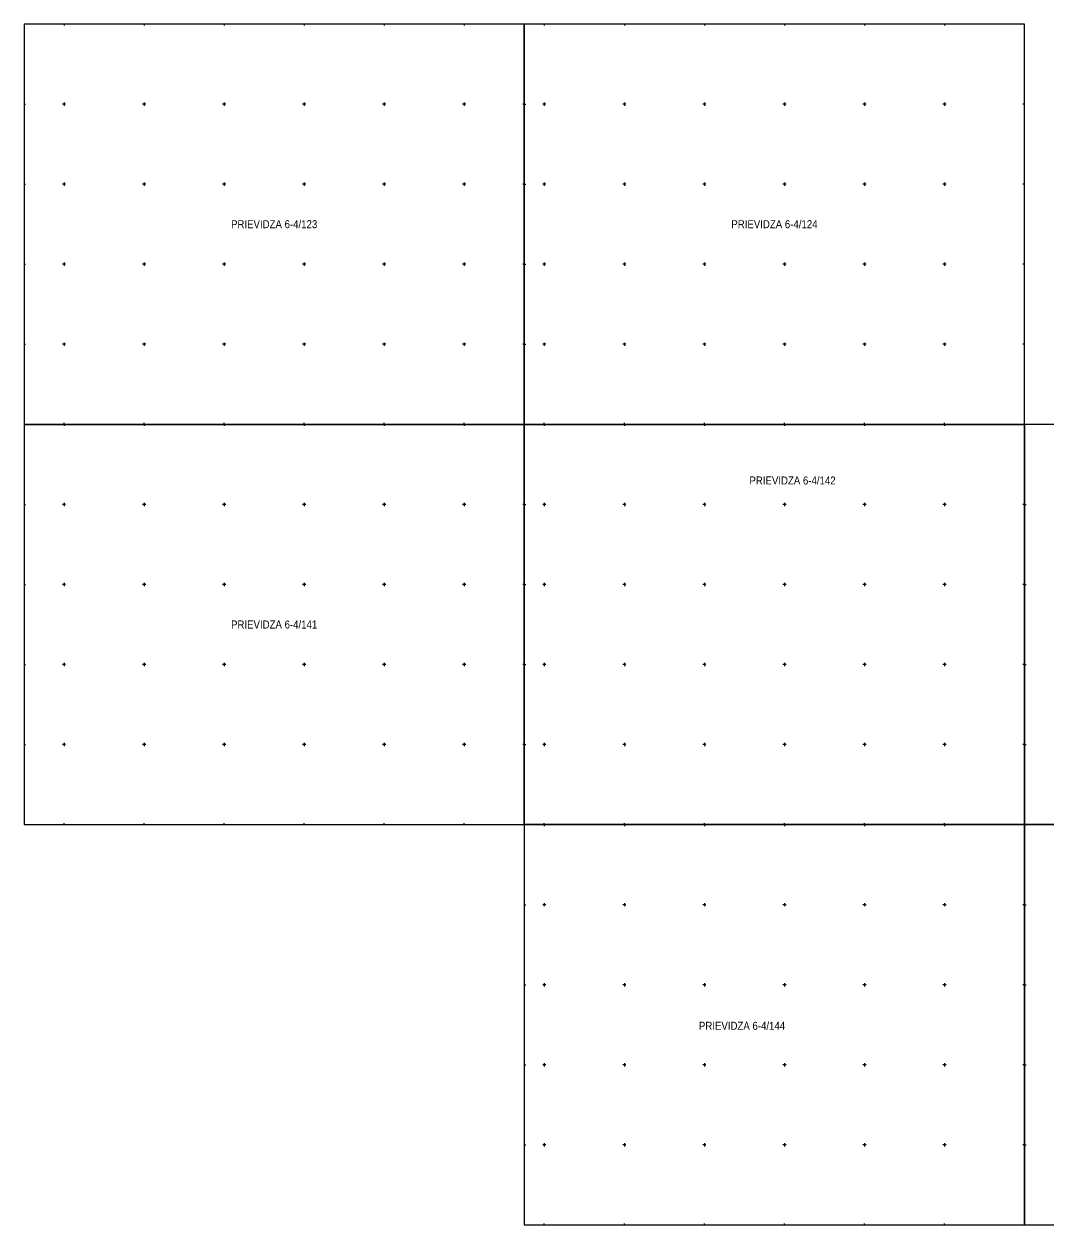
# Model space of a CAD drawing. Extents: x -46688 to -46438, y -123000 to -122825.
# Drawn here: x -46687.5 to -46623.7, y -122900 to -122825 of the extents above; entities that cross this region are included whole.
import ezdxf
from ezdxf.enums import TextEntityAlignment as Align

# ---------------------------------------------------------------- set-up
doc = ezdxf.new("R2010")
doc.units = 0
doc.header["$LTSCALE"] = 0.2
doc.layers.add('17', color=7, linetype='Continuous', lineweight=13)
doc.layers.add('18', color=7, linetype='Continuous', lineweight=13)
doc.layers.add('19', color=7, linetype='Continuous')

msp = doc.modelspace()

# ---------------------------------------------------------------- linework, layer by layer
at = {"layer": '17'}
for points in [[(-46656.25, -122825), (-46687.5, -122825), (-46687.5, -122850), (-46656.25, -122850)], [(-46625, -122825), (-46656.25, -122825), (-46656.25, -122850), (-46625, -122850)], [(-46656.25, -122850), (-46687.5, -122850), (-46687.5, -122875), (-46656.25, -122875)], [(-46625, -122850), (-46656.25, -122850), (-46656.25, -122875), (-46625, -122875)], [(-46593.75, -122850), (-46625, -122850), (-46625, -122875), (-46593.75, -122875)], [(-46625, -122875), (-46656.25, -122875), (-46656.25, -122900), (-46625, -122900)], [(-46593.75, -122875), (-46625, -122875), (-46625, -122900), (-46593.75, -122900)]]:
    msp.add_lwpolyline(points, close=True, dxfattribs=at)
at = {"layer": '18'}
for p, q in [((-46685, -122825), (-46685, -122825.1)), ((-46685, -122825), (-46685, -122825.1)), ((-46685, -122825), (-46685, -122825.1)), ((-46685, -122825), (-46685, -122825.1)), ((-46680, -122825), (-46680, -122825.1)), ((-46680, -122825), (-46680, -122825.1)), ((-46680, -122825), (-46680, -122825.1)), ((-46680, -122825), (-46680, -122825.1)), ((-46675, -122825), (-46675, -122825.1)), ((-46675, -122825), (-46675, -122825.1)), ((-46675, -122825), (-46675, -122825.1)), ((-46675, -122825), (-46675, -122825.1)), ((-46670, -122825), (-46670, -122825.1)), ((-46670, -122825), (-46670, -122825.1)), ((-46670, -122825), (-46670, -122825.1)), ((-46670, -122825), (-46670, -122825.1)), ((-46665, -122825), (-46665, -122825.1)), ((-46665, -122825), (-46665, -122825.1)), ((-46665, -122825), (-46665, -122825.1)), ((-46665, -122825), (-46665, -122825.1)), ((-46660, -122825), (-46660, -122825.1)), ((-46660, -122825), (-46660, -122825.1)), ((-46660, -122825), (-46660, -122825.1)), ((-46660, -122825), (-46660, -122825.1)), ((-46655, -122825), (-46655, -122825.1)), ((-46655, -122825), (-46655, -122825.1)), ((-46655, -122825), (-46655, -122825.1)), ((-46655, -122825), (-46655, -122825.1)), ((-46650, -122825), (-46650, -122825.1)), ((-46650, -122825), (-46650, -122825.1)), ((-46650, -122825), (-46650, -122825.1)), ((-46650, -122825), (-46650, -122825.1)), ((-46645, -122825), (-46645, -122825.1)), ((-46645, -122825), (-46645, -122825.1)), ((-46645, -122825), (-46645, -122825.1)), ((-46645, -122825), (-46645, -122825.1)), ((-46640, -122825), (-46640, -122825.1)), ((-46640, -122825), (-46640, -122825.1)), ((-46640, -122825), (-46640, -122825.1)), ((-46640, -122825), (-46640, -122825.1)), ((-46635, -122825), (-46635, -122825.1)), ((-46635, -122825), (-46635, -122825.1)), ((-46635, -122825), (-46635, -122825.1)), ((-46635, -122825), (-46635, -122825.1)), ((-46630, -122825), (-46630, -122825.1)), ((-46630, -122825), (-46630, -122825.1)), ((-46630, -122825), (-46630, -122825.1)), ((-46630, -122825), (-46630, -122825.1)), ((-46687.5, -122830), (-46687.4, -122830)), ((-46684.9, -122830), (-46685.1, -122830)), ((-46685, -122829.9), (-46685, -122830.1)), ((-46679.9, -122830), (-46680.1, -122830)), ((-46680, -122829.9), (-46680, -122830.1)), ((-46674.9, -122830), (-46675.1, -122830)), ((-46675, -122829.9), (-46675, -122830.1)), ((-46669.9, -122830), (-46670.1, -122830)), ((-46670, -122829.9), (-46670, -122830.1)), ((-46664.9, -122830), (-46665.1, -122830)), ((-46665, -122829.9), (-46665, -122830.1)), ((-46659.9, -122830), (-46660.1, -122830)), ((-46660, -122829.9), (-46660, -122830.1)), ((-46656.25, -122830), (-46656.35, -122830)), ((-46656.25, -122830), (-46656.15, -122830)), ((-46654.9, -122830), (-46655.1, -122830)), ((-46655, -122829.9), (-46655, -122830.1)), ((-46649.9, -122830), (-46650.1, -122830)), ((-46650, -122829.9), (-46650, -122830.1)), ((-46644.9, -122830), (-46645.1, -122830)), ((-46645, -122829.9), (-46645, -122830.1)), ((-46639.9, -122830), (-46640.1, -122830)), ((-46640, -122829.9), (-46640, -122830.1)), ((-46634.9, -122830), (-46635.1, -122830)), ((-46635, -122829.9), (-46635, -122830.1)), ((-46629.9, -122830), (-46630.1, -122830)), ((-46630, -122829.9), (-46630, -122830.1)), ((-46625, -122830), (-46625.1, -122830)), ((-46687.5, -122835), (-46687.4, -122835)), ((-46684.9, -122835), (-46685.1, -122835)), ((-46685, -122834.9), (-46685, -122835.1)), ((-46679.9, -122835), (-46680.1, -122835)), ((-46680, -122834.9), (-46680, -122835.1)), ((-46674.9, -122835), (-46675.1, -122835)), ((-46675, -122834.9), (-46675, -122835.1)), ((-46669.9, -122835), (-46670.1, -122835)), ((-46670, -122834.9), (-46670, -122835.1)), ((-46664.9, -122835), (-46665.1, -122835)), ((-46665, -122834.9), (-46665, -122835.1)), ((-46659.9, -122835), (-46660.1, -122835)), ((-46660, -122834.9), (-46660, -122835.1)), ((-46656.25, -122835), (-46656.35, -122835)), ((-46656.25, -122835), (-46656.15, -122835)), ((-46654.9, -122835), (-46655.1, -122835)), ((-46655, -122834.9), (-46655, -122835.1)), ((-46649.9, -122835), (-46650.1, -122835)), ((-46650, -122834.9), (-46650, -122835.1)), ((-46644.9, -122835), (-46645.1, -122835)), ((-46645, -122834.9), (-46645, -122835.1)), ((-46639.9, -122835), (-46640.1, -122835)), ((-46640, -122834.9), (-46640, -122835.1)), ((-46634.9, -122835), (-46635.1, -122835)), ((-46635, -122834.9), (-46635, -122835.1)), ((-46629.9, -122835), (-46630.1, -122835)), ((-46630, -122834.9), (-46630, -122835.1)), ((-46625, -122835), (-46625.1, -122835)), ((-46687.5, -122840), (-46687.4, -122840)), ((-46684.9, -122840), (-46685.1, -122840)), ((-46685, -122839.9), (-46685, -122840.1)), ((-46679.9, -122840), (-46680.1, -122840)), ((-46680, -122839.9), (-46680, -122840.1)), ((-46674.9, -122840), (-46675.1, -122840)), ((-46675, -122839.9), (-46675, -122840.1)), ((-46669.9, -122840), (-46670.1, -122840)), ((-46670, -122839.9), (-46670, -122840.1)), ((-46664.9, -122840), (-46665.1, -122840)), ((-46665, -122839.9), (-46665, -122840.1)), ((-46659.9, -122840), (-46660.1, -122840)), ((-46660, -122839.9), (-46660, -122840.1)), ((-46656.25, -122840), (-46656.35, -122840)), ((-46656.25, -122840), (-46656.15, -122840)), ((-46654.9, -122840), (-46655.1, -122840)), ((-46655, -122839.9), (-46655, -122840.1)), ((-46649.9, -122840), (-46650.1, -122840)), ((-46650, -122839.9), (-46650, -122840.1)), ((-46644.9, -122840), (-46645.1, -122840)), ((-46645, -122839.9), (-46645, -122840.1)), ((-46639.9, -122840), (-46640.1, -122840)), ((-46640, -122839.9), (-46640, -122840.1)), ((-46634.9, -122840), (-46635.1, -122840)), ((-46635, -122839.9), (-46635, -122840.1)), ((-46629.9, -122840), (-46630.1, -122840)), ((-46630, -122839.9), (-46630, -122840.1)), ((-46625, -122840), (-46625.1, -122840)), ((-46687.5, -122845), (-46687.4, -122845)), ((-46684.9, -122845), (-46685.1, -122845)), ((-46685, -122844.9), (-46685, -122845.1)), ((-46679.9, -122845), (-46680.1, -122845)), ((-46680, -122844.9), (-46680, -122845.1)), ((-46674.9, -122845), (-46675.1, -122845)), ((-46675, -122844.9), (-46675, -122845.1)), ((-46669.9, -122845), (-46670.1, -122845)), ((-46670, -122844.9), (-46670, -122845.1)), ((-46664.9, -122845), (-46665.1, -122845)), ((-46665, -122844.9), (-46665, -122845.1)), ((-46659.9, -122845), (-46660.1, -122845)), ((-46660, -122844.9), (-46660, -122845.1)), ((-46656.25, -122845), (-46656.35, -122845)), ((-46656.25, -122845), (-46656.15, -122845)), ((-46654.9, -122845), (-46655.1, -122845)), ((-46655, -122844.9), (-46655, -122845.1)), ((-46649.9, -122845), (-46650.1, -122845)), ((-46650, -122844.9), (-46650, -122845.1)), ((-46644.9, -122845), (-46645.1, -122845)), ((-46645, -122844.9), (-46645, -122845.1)), ((-46639.9, -122845), (-46640.1, -122845)), ((-46640, -122844.9), (-46640, -122845.1)), ((-46634.9, -122845), (-46635.1, -122845)), ((-46635, -122844.9), (-46635, -122845.1)), ((-46629.9, -122845), (-46630.1, -122845)), ((-46630, -122844.9), (-46630, -122845.1)), ((-46625, -122845), (-46625.1, -122845)), ((-46685, -122850), (-46685, -122849.9)), ((-46685, -122850), (-46685, -122849.9)), ((-46685, -122850), (-46685, -122849.9)), ((-46685, -122850), (-46685, -122849.9)), ((-46685, -122850), (-46685, -122850.1)), ((-46685, -122850), (-46685, -122850.1)), ((-46685, -122850), (-46685, -122850.1)), ((-46685, -122850), (-46685, -122850.1)), ((-46680, -122850), (-46680, -122849.9)), ((-46680, -122850), (-46680, -122849.9)), ((-46680, -122850), (-46680, -122849.9)), ((-46680, -122850), (-46680, -122849.9)), ((-46680, -122850), (-46680, -122850.1)), ((-46680, -122850), (-46680, -122850.1)), ((-46680, -122850), (-46680, -122850.1)), ((-46680, -122850), (-46680, -122850.1)), ((-46675, -122850), (-46675, -122849.9)), ((-46675, -122850), (-46675, -122849.9)), ((-46675, -122850), (-46675, -122849.9)), ((-46675, -122850), (-46675, -122849.9)), ((-46675, -122850), (-46675, -122850.1)), ((-46675, -122850), (-46675, -122850.1)), ((-46675, -122850), (-46675, -122850.1)), ((-46675, -122850), (-46675, -122850.1)), ((-46670, -122850), (-46670, -122849.9)), ((-46670, -122850), (-46670, -122849.9)), ((-46670, -122850), (-46670, -122849.9)), ((-46670, -122850), (-46670, -122849.9)), ((-46670, -122850), (-46670, -122850.1)), ((-46670, -122850), (-46670, -122850.1)), ((-46670, -122850), (-46670, -122850.1)), ((-46670, -122850), (-46670, -122850.1)), ((-46665, -122850), (-46665, -122849.9)), ((-46665, -122850), (-46665, -122849.9)), ((-46665, -122850), (-46665, -122849.9)), ((-46665, -122850), (-46665, -122849.9)), ((-46665, -122850), (-46665, -122850.1)), ((-46665, -122850), (-46665, -122850.1)), ((-46665, -122850), (-46665, -122850.1)), ((-46665, -122850), (-46665, -122850.1)), ((-46660, -122850), (-46660, -122849.9)), ((-46660, -122850), (-46660, -122849.9)), ((-46660, -122850), (-46660, -122849.9)), ((-46660, -122850), (-46660, -122849.9)), ((-46660, -122850), (-46660, -122850.1)), ((-46660, -122850), (-46660, -122850.1)), ((-46660, -122850), (-46660, -122850.1)), ((-46660, -122850), (-46660, -122850.1)), ((-46655, -122850), (-46655, -122849.9)), ((-46655, -122850), (-46655, -122849.9)), ((-46655, -122850), (-46655, -122849.9)), ((-46655, -122850), (-46655, -122849.9)), ((-46655, -122850), (-46655, -122850.1)), ((-46655, -122850), (-46655, -122850.1)), ((-46655, -122850), (-46655, -122850.1)), ((-46655, -122850), (-46655, -122850.1)), ((-46650, -122850), (-46650, -122849.9)), ((-46650, -122850), (-46650, -122849.9)), ((-46650, -122850), (-46650, -122849.9)), ((-46650, -122850), (-46650, -122849.9)), ((-46650, -122850), (-46650, -122850.1)), ((-46650, -122850), (-46650, -122850.1)), ((-46650, -122850), (-46650, -122850.1)), ((-46650, -122850), (-46650, -122850.1)), ((-46645, -122850), (-46645, -122849.9)), ((-46645, -122850), (-46645, -122849.9)), ((-46645, -122850), (-46645, -122849.9)), ((-46645, -122850), (-46645, -122849.9)), ((-46645, -122850), (-46645, -122850.1)), ((-46645, -122850), (-46645, -122850.1)), ((-46645, -122850), (-46645, -122850.1)), ((-46645, -122850), (-46645, -122850.1)), ((-46640, -122850), (-46640, -122849.9)), ((-46640, -122850), (-46640, -122849.9)), ((-46640, -122850), (-46640, -122849.9)), ((-46640, -122850), (-46640, -122849.9)), ((-46640, -122850), (-46640, -122850.1)), ((-46640, -122850), (-46640, -122850.1)), ((-46640, -122850), (-46640, -122850.1)), ((-46640, -122850), (-46640, -122850.1)), ((-46635, -122850), (-46635, -122849.9)), ((-46635, -122850), (-46635, -122849.9)), ((-46635, -122850), (-46635, -122849.9)), ((-46635, -122850), (-46635, -122849.9)), ((-46635, -122850), (-46635, -122850.1)), ((-46635, -122850), (-46635, -122850.1)), ((-46635, -122850), (-46635, -122850.1)), ((-46635, -122850), (-46635, -122850.1)), ((-46630, -122850), (-46630, -122849.9)), ((-46630, -122850), (-46630, -122849.9)), ((-46630, -122850), (-46630, -122849.9)), ((-46630, -122850), (-46630, -122849.9)), ((-46630, -122850), (-46630, -122850.1)), ((-46630, -122850), (-46630, -122850.1)), ((-46630, -122850), (-46630, -122850.1)), ((-46630, -122850), (-46630, -122850.1)), ((-46687.5, -122855), (-46687.4, -122855)), ((-46684.9, -122855), (-46685.1, -122855)), ((-46685, -122854.9), (-46685, -122855.1)), ((-46679.9, -122855), (-46680.1, -122855)), ((-46680, -122854.9), (-46680, -122855.1)), ((-46674.9, -122855), (-46675.1, -122855)), ((-46675, -122854.9), (-46675, -122855.1)), ((-46669.9, -122855), (-46670.1, -122855)), ((-46670, -122854.9), (-46670, -122855.1)), ((-46664.9, -122855), (-46665.1, -122855)), ((-46665, -122854.9), (-46665, -122855.1)), ((-46659.9, -122855), (-46660.1, -122855)), ((-46660, -122854.9), (-46660, -122855.1)), ((-46656.25, -122855), (-46656.35, -122855)), ((-46656.25, -122855), (-46656.15, -122855)), ((-46654.9, -122855), (-46655.1, -122855)), ((-46655, -122854.9), (-46655, -122855.1)), ((-46649.9, -122855), (-46650.1, -122855)), ((-46650, -122854.9), (-46650, -122855.1)), ((-46644.9, -122855), (-46645.1, -122855)), ((-46645, -122854.9), (-46645, -122855.1)), ((-46639.9, -122855), (-46640.1, -122855)), ((-46640, -122854.9), (-46640, -122855.1)), ((-46634.9, -122855), (-46635.1, -122855)), ((-46635, -122854.9), (-46635, -122855.1)), ((-46629.9, -122855), (-46630.1, -122855)), ((-46630, -122854.9), (-46630, -122855.1)), ((-46625, -122855), (-46625.1, -122855)), ((-46625, -122855), (-46624.9, -122855)), ((-46687.5, -122860), (-46687.4, -122860)), ((-46684.9, -122860), (-46685.1, -122860)), ((-46685, -122859.9), (-46685, -122860.1)), ((-46679.9, -122860), (-46680.1, -122860)), ((-46680, -122859.9), (-46680, -122860.1)), ((-46674.9, -122860), (-46675.1, -122860)), ((-46675, -122859.9), (-46675, -122860.1)), ((-46669.9, -122860), (-46670.1, -122860)), ((-46670, -122859.9), (-46670, -122860.1)), ((-46664.9, -122860), (-46665.1, -122860)), ((-46665, -122859.9), (-46665, -122860.1)), ((-46659.9, -122860), (-46660.1, -122860)), ((-46660, -122859.9), (-46660, -122860.1)), ((-46656.25, -122860), (-46656.35, -122860)), ((-46656.25, -122860), (-46656.15, -122860)), ((-46654.9, -122860), (-46655.1, -122860)), ((-46655, -122859.9), (-46655, -122860.1)), ((-46649.9, -122860), (-46650.1, -122860)), ((-46650, -122859.9), (-46650, -122860.1)), ((-46644.9, -122860), (-46645.1, -122860)), ((-46645, -122859.9), (-46645, -122860.1)), ((-46639.9, -122860), (-46640.1, -122860)), ((-46640, -122859.9), (-46640, -122860.1)), ((-46634.9, -122860), (-46635.1, -122860)), ((-46635, -122859.9), (-46635, -122860.1)), ((-46629.9, -122860), (-46630.1, -122860)), ((-46630, -122859.9), (-46630, -122860.1)), ((-46625, -122860), (-46625.1, -122860)), ((-46625, -122860), (-46624.9, -122860)), ((-46687.5, -122865), (-46687.4, -122865)), ((-46684.9, -122865), (-46685.1, -122865)), ((-46685, -122864.9), (-46685, -122865.1)), ((-46679.9, -122865), (-46680.1, -122865)), ((-46680, -122864.9), (-46680, -122865.1)), ((-46674.9, -122865), (-46675.1, -122865)), ((-46675, -122864.9), (-46675, -122865.1)), ((-46669.9, -122865), (-46670.1, -122865)), ((-46670, -122864.9), (-46670, -122865.1)), ((-46664.9, -122865), (-46665.1, -122865)), ((-46665, -122864.9), (-46665, -122865.1)), ((-46659.9, -122865), (-46660.1, -122865)), ((-46660, -122864.9), (-46660, -122865.1)), ((-46656.25, -122865), (-46656.35, -122865)), ((-46656.25, -122865), (-46656.15, -122865)), ((-46654.9, -122865), (-46655.1, -122865)), ((-46655, -122864.9), (-46655, -122865.1)), ((-46649.9, -122865), (-46650.1, -122865)), ((-46650, -122864.9), (-46650, -122865.1)), ((-46644.9, -122865), (-46645.1, -122865)), ((-46645, -122864.9), (-46645, -122865.1)), ((-46639.9, -122865), (-46640.1, -122865)), ((-46640, -122864.9), (-46640, -122865.1)), ((-46634.9, -122865), (-46635.1, -122865)), ((-46635, -122864.9), (-46635, -122865.1)), ((-46629.9, -122865), (-46630.1, -122865)), ((-46630, -122864.9), (-46630, -122865.1)), ((-46625, -122865), (-46625.1, -122865)), ((-46625, -122865), (-46624.9, -122865)), ((-46687.5, -122870), (-46687.4, -122870)), ((-46684.9, -122870), (-46685.1, -122870)), ((-46685, -122869.9), (-46685, -122870.1)), ((-46679.9, -122870), (-46680.1, -122870)), ((-46680, -122869.9), (-46680, -122870.1)), ((-46674.9, -122870), (-46675.1, -122870)), ((-46675, -122869.9), (-46675, -122870.1)), ((-46669.9, -122870), (-46670.1, -122870)), ((-46670, -122869.9), (-46670, -122870.1)), ((-46664.9, -122870), (-46665.1, -122870)), ((-46665, -122869.9), (-46665, -122870.1)), ((-46659.9, -122870), (-46660.1, -122870)), ((-46660, -122869.9), (-46660, -122870.1)), ((-46656.25, -122870), (-46656.35, -122870)), ((-46656.25, -122870), (-46656.15, -122870)), ((-46654.9, -122870), (-46655.1, -122870)), ((-46655, -122869.9), (-46655, -122870.1)), ((-46649.9, -122870), (-46650.1, -122870)), ((-46650, -122869.9), (-46650, -122870.1)), ((-46644.9, -122870), (-46645.1, -122870)), ((-46645, -122869.9), (-46645, -122870.1)), ((-46639.9, -122870), (-46640.1, -122870)), ((-46640, -122869.9), (-46640, -122870.1)), ((-46634.9, -122870), (-46635.1, -122870)), ((-46635, -122869.9), (-46635, -122870.1)), ((-46629.9, -122870), (-46630.1, -122870)), ((-46630, -122869.9), (-46630, -122870.1)), ((-46625, -122870), (-46625.1, -122870)), ((-46625, -122870), (-46624.9, -122870)), ((-46685, -122875), (-46685, -122874.9)), ((-46685, -122875), (-46685, -122874.9)), ((-46685, -122875), (-46685, -122874.9)), ((-46685, -122875), (-46685, -122874.9)), ((-46680, -122875), (-46680, -122874.9)), ((-46680, -122875), (-46680, -122874.9)), ((-46680, -122875), (-46680, -122874.9)), ((-46680, -122875), (-46680, -122874.9)), ((-46675, -122875), (-46675, -122874.9)), ((-46675, -122875), (-46675, -122874.9)), ((-46675, -122875), (-46675, -122874.9)), ((-46675, -122875), (-46675, -122874.9)), ((-46670, -122875), (-46670, -122874.9)), ((-46670, -122875), (-46670, -122874.9)), ((-46670, -122875), (-46670, -122874.9)), ((-46670, -122875), (-46670, -122874.9)), ((-46665, -122875), (-46665, -122874.9)), ((-46665, -122875), (-46665, -122874.9)), ((-46665, -122875), (-46665, -122874.9)), ((-46665, -122875), (-46665, -122874.9)), ((-46660, -122875), (-46660, -122874.9)), ((-46660, -122875), (-46660, -122874.9)), ((-46660, -122875), (-46660, -122874.9)), ((-46660, -122875), (-46660, -122874.9)), ((-46655, -122875), (-46655, -122874.9)), ((-46655, -122875), (-46655, -122874.9)), ((-46655, -122875), (-46655, -122874.9)), ((-46655, -122875), (-46655, -122874.9)), ((-46655, -122875), (-46655, -122875.1)), ((-46655, -122875), (-46655, -122875.1)), ((-46655, -122875), (-46655, -122875.1)), ((-46655, -122875), (-46655, -122875.1)), ((-46650, -122875), (-46650, -122874.9)), ((-46650, -122875), (-46650, -122874.9)), ((-46650, -122875), (-46650, -122874.9)), ((-46650, -122875), (-46650, -122874.9)), ((-46650, -122875), (-46650, -122875.1)), ((-46650, -122875), (-46650, -122875.1)), ((-46650, -122875), (-46650, -122875.1)), ((-46650, -122875), (-46650, -122875.1)), ((-46645, -122875), (-46645, -122874.9)), ((-46645, -122875), (-46645, -122874.9)), ((-46645, -122875), (-46645, -122874.9)), ((-46645, -122875), (-46645, -122874.9)), ((-46645, -122875), (-46645, -122875.1)), ((-46645, -122875), (-46645, -122875.1)), ((-46645, -122875), (-46645, -122875.1)), ((-46645, -122875), (-46645, -122875.1)), ((-46640, -122875), (-46640, -122874.9)), ((-46640, -122875), (-46640, -122874.9)), ((-46640, -122875), (-46640, -122874.9)), ((-46640, -122875), (-46640, -122874.9)), ((-46640, -122875), (-46640, -122875.1)), ((-46640, -122875), (-46640, -122875.1)), ((-46640, -122875), (-46640, -122875.1)), ((-46640, -122875), (-46640, -122875.1)), ((-46635, -122875), (-46635, -122874.9)), ((-46635, -122875), (-46635, -122874.9)), ((-46635, -122875), (-46635, -122874.9)), ((-46635, -122875), (-46635, -122874.9)), ((-46635, -122875), (-46635, -122875.1)), ((-46635, -122875), (-46635, -122875.1)), ((-46635, -122875), (-46635, -122875.1)), ((-46635, -122875), (-46635, -122875.1)), ((-46630, -122875), (-46630, -122874.9)), ((-46630, -122875), (-46630, -122874.9)), ((-46630, -122875), (-46630, -122874.9)), ((-46630, -122875), (-46630, -122874.9)), ((-46630, -122875), (-46630, -122875.1)), ((-46630, -122875), (-46630, -122875.1)), ((-46630, -122875), (-46630, -122875.1)), ((-46630, -122875), (-46630, -122875.1)), ((-46656.25, -122880), (-46656.15, -122880)), ((-46654.9, -122880), (-46655.1, -122880)), ((-46655, -122879.9), (-46655, -122880.1)), ((-46649.9, -122880), (-46650.1, -122880)), ((-46650, -122879.9), (-46650, -122880.1)), ((-46644.9, -122880), (-46645.1, -122880)), ((-46645, -122879.9), (-46645, -122880.1)), ((-46639.9, -122880), (-46640.1, -122880)), ((-46640, -122879.9), (-46640, -122880.1)), ((-46634.9, -122880), (-46635.1, -122880)), ((-46635, -122879.9), (-46635, -122880.1)), ((-46629.9, -122880), (-46630.1, -122880)), ((-46630, -122879.9), (-46630, -122880.1)), ((-46625, -122880), (-46625.1, -122880)), ((-46625, -122880), (-46624.9, -122880)), ((-46656.25, -122885), (-46656.15, -122885)), ((-46654.9, -122885), (-46655.1, -122885)), ((-46655, -122884.9), (-46655, -122885.1)), ((-46649.9, -122885), (-46650.1, -122885)), ((-46650, -122884.9), (-46650, -122885.1)), ((-46644.9, -122885), (-46645.1, -122885)), ((-46645, -122884.9), (-46645, -122885.1)), ((-46639.9, -122885), (-46640.1, -122885)), ((-46640, -122884.9), (-46640, -122885.1)), ((-46634.9, -122885), (-46635.1, -122885)), ((-46635, -122884.9), (-46635, -122885.1)), ((-46629.9, -122885), (-46630.1, -122885)), ((-46630, -122884.9), (-46630, -122885.1)), ((-46625, -122885), (-46625.1, -122885)), ((-46625, -122885), (-46624.9, -122885)), ((-46656.25, -122890), (-46656.15, -122890)), ((-46654.9, -122890), (-46655.1, -122890)), ((-46655, -122889.9), (-46655, -122890.1)), ((-46649.9, -122890), (-46650.1, -122890)), ((-46650, -122889.9), (-46650, -122890.1)), ((-46644.9, -122890), (-46645.1, -122890)), ((-46645, -122889.9), (-46645, -122890.1)), ((-46639.9, -122890), (-46640.1, -122890)), ((-46640, -122889.9), (-46640, -122890.1)), ((-46634.9, -122890), (-46635.1, -122890)), ((-46635, -122889.9), (-46635, -122890.1)), ((-46629.9, -122890), (-46630.1, -122890)), ((-46630, -122889.9), (-46630, -122890.1)), ((-46625, -122890), (-46625.1, -122890)), ((-46625, -122890), (-46624.9, -122890)), ((-46656.25, -122895), (-46656.15, -122895)), ((-46654.9, -122895), (-46655.1, -122895)), ((-46655, -122894.9), (-46655, -122895.1)), ((-46649.9, -122895), (-46650.1, -122895)), ((-46650, -122894.9), (-46650, -122895.1)), ((-46644.9, -122895), (-46645.1, -122895)), ((-46645, -122894.9), (-46645, -122895.1)), ((-46639.9, -122895), (-46640.1, -122895)), ((-46640, -122894.9), (-46640, -122895.1)), ((-46634.9, -122895), (-46635.1, -122895)), ((-46635, -122894.9), (-46635, -122895.1)), ((-46629.9, -122895), (-46630.1, -122895)), ((-46630, -122894.9), (-46630, -122895.1)), ((-46625, -122895), (-46625.1, -122895)), ((-46625, -122895), (-46624.9, -122895)), ((-46655, -122900), (-46655, -122899.9)), ((-46655, -122900), (-46655, -122899.9)), ((-46655, -122900), (-46655, -122899.9)), ((-46655, -122900), (-46655, -122899.9)), ((-46650, -122900), (-46650, -122899.9)), ((-46650, -122900), (-46650, -122899.9)), ((-46650, -122900), (-46650, -122899.9)), ((-46650, -122900), (-46650, -122899.9)), ((-46645, -122900), (-46645, -122899.9)), ((-46645, -122900), (-46645, -122899.9)), ((-46645, -122900), (-46645, -122899.9)), ((-46645, -122900), (-46645, -122899.9)), ((-46640, -122900), (-46640, -122899.9)), ((-46640, -122900), (-46640, -122899.9)), ((-46640, -122900), (-46640, -122899.9)), ((-46640, -122900), (-46640, -122899.9)), ((-46635, -122900), (-46635, -122899.9)), ((-46635, -122900), (-46635, -122899.9)), ((-46635, -122900), (-46635, -122899.9)), ((-46635, -122900), (-46635, -122899.9)), ((-46630, -122900), (-46630, -122899.9)), ((-46630, -122900), (-46630, -122899.9)), ((-46630, -122900), (-46630, -122899.9)), ((-46630, -122900), (-46630, -122899.9))]:
    msp.add_line(p, q, dxfattribs=at)

# ---------------------------------------------------------------- texts
at = {"layer": '19', "width": 0.9}
for s, p in [('PRIEVIDZA 6-4/123', (-46671.875, -122837.75)), ('PRIEVIDZA 6-4/124', (-46640.625, -122837.75)), ('PRIEVIDZA 6-4/142', (-46639.495, -122853.757)), ('PRIEVIDZA 6-4/141', (-46671.875, -122862.75)), ('PRIEVIDZA 6-4/144', (-46642.648, -122887.812))]:
    msp.add_text(s, height=0.5, dxfattribs=at).set_placement(p, align=Align.CENTER)

doc.saveas('drawing.dxf')
